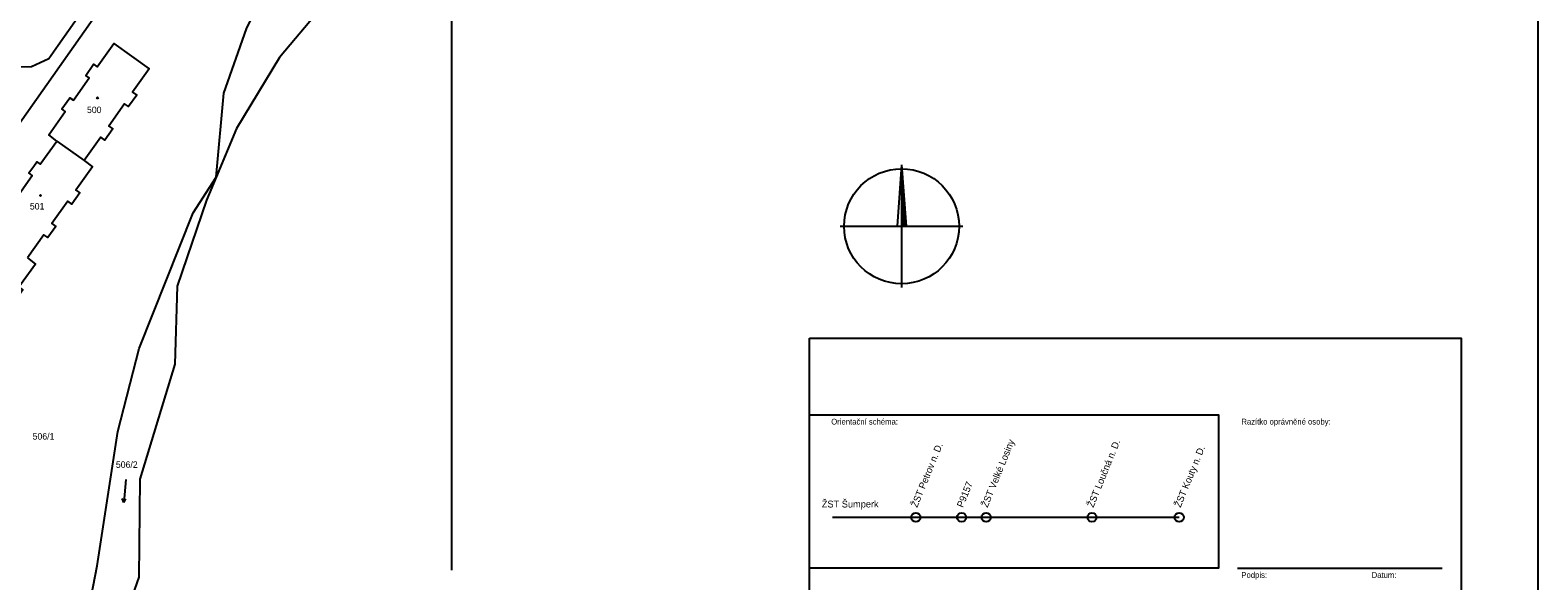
# Model space of a CAD drawing. Extents: x -558500 to -557517, y -1073973 to -1073051.
# Drawn here: x -557909.9 to -557516.5, y -1073570.4 to -1073426.7 of the extents above; entities that cross this region are included whole.
import ezdxf

# ---------------------------------------------------------------- set-up
doc = ezdxf.new("R2010")
doc.units = 0
for name, color, linetype in [('Default', 7, 'Continuous'), ('Hranice parcel', 7, 'Continuous'), ('Parcelní čísla', 7, 'Continuous'), ('ROZPISKA', 7, 'Continuous'), ('Rozpiska_pola_3', 7, 'Continuous'), ('Rozpiska_pole_1', 7, 'Continuous'), ('Rozpiska_pole_2', 7, 'Continuous'), ('Rozpiska_pole_7', 7, 'Continuous'), ('Vrstva 1', 7, 'Continuous'), ('Značky budov', 7, 'Continuous'), ('Značky kultur', 7, 'Continuous')]:
    doc.layers.add(name, color=color, linetype=linetype)

# ---------------------------------------------------------------- blocks, each defined once
blk = doc.blocks.new('_U2')
at = {"layer": 'Rozpiska_pola_3'}
blk.add_line((-2.6675, -1.82505), (2.6675, -1.82505), dxfattribs=at)
for s, p in [('Razítko oprávněné osoby:', (-2.5675, 1.92495)), ('Podpis:', (-2.5675, -2.07505)), ('Datum:', (0.8325, -2.07505))]:
    blk.add_text(s, height=0.15, dxfattribs=at).set_placement(p)
blk = doc.blocks.new('_U3')
at = {"layer": 'Rozpiska_pole_2'}
blk.add_lwpolyline([(-5.33255, 2.00005), (5.33245, 2.00005), (5.33245, -1.99995), (-5.33255, -1.99995)], close=True, dxfattribs=at)
blk.add_text('Orientační schéma:', height=0.15, dxfattribs=at).set_placement((-4.76755, 1.75005))

msp = doc.modelspace()

# ---------------------------------------------------------------- linework, layer by layer
at = {"layer": 'Default'}
msp.add_lwpolyline([(-557909.21, -1073700), (-558500, -1073700), (-558500, -1073200), (-557800, -1073200), (-557800, -1073567.6)], dxfattribs=at)
for centre in [(-557678.82, -1073553.79), (-557678.82, -1073553.79), (-557666.88, -1073553.79), (-557666.88, -1073553.79)]:
    msp.add_circle(centre, 1.2, dxfattribs=at)
at = {"layer": 'Hranice parcel'}
for p, q in [((-557902.93, -1073455.63), (-557895.8, -1073460.74)), ((-557872.13, -1073513.82), (-557881.3, -1073543.83))]:
    msp.add_line(p, q, dxfattribs=at)
for points in [[(-558022.09, -1073311.21), (-558020.08, -1073313.87), (-558000.41, -1073328.2), (-557993.92, -1073334.5), (-557986.04, -1073343.93), (-557967.1, -1073369.2), (-557918.24, -1073434.51), (-557914.64, -1073436.24), (-557909.55, -1073436.22), (-557905.05, -1073434.1), (-557902.57, -1073430.65), (-557891.22, -1073414.37), (-557877.97, -1073395.43)], [(-557861.36, -1073465.07), (-557859.38, -1073443.12), (-557853.44, -1073426.35), (-557845.8, -1073410.81), (-557826.12, -1073387.26)], [(-557875.08, -1073418.52), (-557880.11, -1073415), (-557884.66, -1073414.11), (-557888.78, -1073417.07), (-557919.08, -1073460.09), (-557919.51, -1073465.45), (-557958.15, -1073519.56), (-557960.76, -1073525.37), (-557961.25, -1073531.9), (-557959.85, -1073543.64), (-557958.52, -1073546.41), (-557955.67, -1073549.33), (-557941.9, -1073559.58)], [(-557834.15, -1073421.11), (-557844.86, -1073433.81), (-557856.07, -1073452.41), (-557861.36, -1073465.07)], [(-557902.93, -1073455.63), (-557905.05, -1073454), (-557900.72, -1073447.94), (-557901.66, -1073447.27), (-557899.55, -1073444.33), (-557898.62, -1073444.99), (-557894.46, -1073439.18), (-557895.4, -1073438.51), (-557893.33, -1073435.61), (-557892.39, -1073436.28), (-557888.07, -1073430.23), (-557878.84, -1073436.82), (-557883.15, -1073442.9), (-557882.08, -1073443.65), (-557884.22, -1073446.66), (-557885.28, -1073445.91), (-557889.41, -1073451.73), (-557888.35, -1073452.48), (-557890.43, -1073455.41), (-557891.49, -1073454.66), (-557895.8, -1073460.74)], [(-557917.76, -1073481.02), (-557919.89, -1073479.42), (-557915.58, -1073473.37), (-557916.49, -1073472.72), (-557914.4, -1073469.79), (-557913.49, -1073470.44), (-557909.33, -1073464.6), (-557910.24, -1073463.95), (-557908.96, -1073462.17), (-557908.15, -1073461.02), (-557907.24, -1073461.67), (-557902.93, -1073455.63)], [(-557895.8, -1073460.74), (-557893.65, -1073462.39), (-557897.97, -1073468.43), (-557896.94, -1073469.17), (-557899.02, -1073472.08), (-557900.05, -1073471.34), (-557904.22, -1073477.17), (-557903.16, -1073477.93), (-557905.25, -1073480.84), (-557906.3, -1073480.09), (-557910.62, -1073486.13)], [(-557897.48, -1073592.57), (-557892.38, -1073566.43), (-557887.02, -1073531.37), (-557881.44, -1073509.74), (-557867.37, -1073474.4), (-557861.36, -1073465.07)], [(-557861.36, -1073465.07), (-557863.88, -1073471.1), (-557871.54, -1073493.51), (-557872.13, -1073513.82)], [(-557910.62, -1073486.13), (-557908.48, -1073487.72), (-557912.81, -1073493.77), (-557911.82, -1073494.47), (-557913.92, -1073497.39), (-557914.9, -1073496.69), (-557919.09, -1073502.55), (-557918.19, -1073503.19), (-557920.29, -1073506.11), (-557921.18, -1073505.47), (-557925.51, -1073511.53)], [(-557881.3, -1073543.83), (-557881.54, -1073569.39), (-557886.18, -1073582.51)]]:
    msp.add_lwpolyline(points, dxfattribs=at)
at = {"layer": 'ROZPISKA'}
msp.add_lwpolyline([(-557700.6, -1073553.79), (-557610.11, -1073553.79)], dxfattribs=at)
for centre in [(-557678.82, -1073553.79), (-557666.88, -1073553.79), (-557660.47, -1073553.79), (-557660.47, -1073553.79), (-557632.86, -1073553.79), (-557632.86, -1073553.79), (-557610.11, -1073553.79), (-557610.11, -1073553.79)]:
    msp.add_circle(centre, 1.2, dxfattribs=at)
at = {"layer": 'Rozpiska_pole_1'}
msp.add_lwpolyline([(-557706.53, -1073507.09), (-557536.53, -1073507.09), (-557536.53, -1073767.09), (-557706.53, -1073767.09)], close=True, dxfattribs=at)
at = {"layer": 'Vrstva 1'}
for p, q in [((-557516.53, -1073190.09), (-557516.53, -1073784.09)), ((-557682.53, -1073461.88), (-557683.68, -1073477.88)), ((-557682.53, -1073461.88), (-557681.35, -1073477.88)), ((-557682.53, -1073461.88), (-557682.53, -1073493.88)), ((-557682.43, -1073464.12), (-557681.46, -1073477.78)), ((-557682.4, -1073477.74), (-557682.43, -1073464.12)), ((-557682.36, -1073466.35), (-557681.56, -1073477.71)), ((-557682.29, -1073477.64), (-557682.36, -1073466.35)), ((-557682.26, -1073468.93), (-557681.66, -1073477.57)), ((-557682.22, -1073477.57), (-557682.26, -1073468.93)), ((-557682.15, -1073471.61), (-557681.77, -1073477.46)), ((-557682.12, -1073477.5), (-557682.15, -1073471.61)), ((-557682.01, -1073474.61), (-557681.87, -1073477.29)), ((-557682.01, -1073477.39), (-557682.01, -1073474.61)), ((-557698.53, -1073477.88), (-557666.53, -1073477.88)), ((-557681.35, -1073477.88), (-557682.4, -1073477.74)), ((-557681.46, -1073477.78), (-557682.29, -1073477.64)), ((-557681.56, -1073477.71), (-557682.22, -1073477.57)), ((-557681.66, -1073477.57), (-557682.12, -1073477.5)), ((-557681.77, -1073477.46), (-557682.01, -1073477.39))]:
    msp.add_line(p, q, dxfattribs=at)
msp.add_circle((-557682.53, -1073477.88), 15, dxfattribs=at)
at = {"layer": 'Značky budov'}
for centre in [(-557892.32, -1073444.4), (-557907.2, -1073469.84)]:
    msp.add_circle(centre, 0.175, dxfattribs=at)
at = {"layer": 'Značky kultur'}
for p, q in [((-557884.95, -1073543.96), (-557885.47, -1073549.94)), ((-557885.47, -1073549.94), (-557885.89, -1073548.92)), ((-557885.47, -1073549.94), (-557884.89, -1073549.01))]:
    msp.add_line(p, q, dxfattribs=at)

# ---------------------------------------------------------------- block references
at = {"layer": 'Rozpiska_pola_3', "xscale": 10, "yscale": 10}
msp.add_blockref('_U2', (-557568.21, -1073548.84), dxfattribs=at)
at = {"layer": 'Rozpiska_pole_2', "xscale": 10, "yscale": 10}
msp.add_blockref('_U3', (-557653.21, -1073547.09), dxfattribs=at)

# ---------------------------------------------------------------- texts
at = {"layer": 'Parcelní čísla'}
for s, p in [('500', (-557895.07, -1073448.35)), ('501', (-557909.97, -1073473.5)), ('506/1', (-557909.25, -1073533.53)), ('506/2', (-557887.53, -1073540.89))]:
    msp.add_text(s, height=1.7, dxfattribs=at).set_placement(p)
at = {"layer": 'Rozpiska_pole_7'}
for s, p in [('ŽST Petrov n. D.', (-557678.47, -1073551.39)), ('ŽST Velké Losiny', (-557660.12, -1073551.39)), ('ŽST Loučná n. D.', (-557632.51, -1073551.39)), ('ŽST Kouty n. D.', (-557609.76, -1073551.39)), ('P9157', (-557666.54, -1073551.39))]:
    msp.add_text(s, height=1.8, rotation=67.8731, dxfattribs=at).set_placement(p)
msp.add_text('ŽST Šumperk', height=1.8, dxfattribs=at).set_placement((-557703.36, -1073551.23))

doc.saveas('drawing.dxf')
